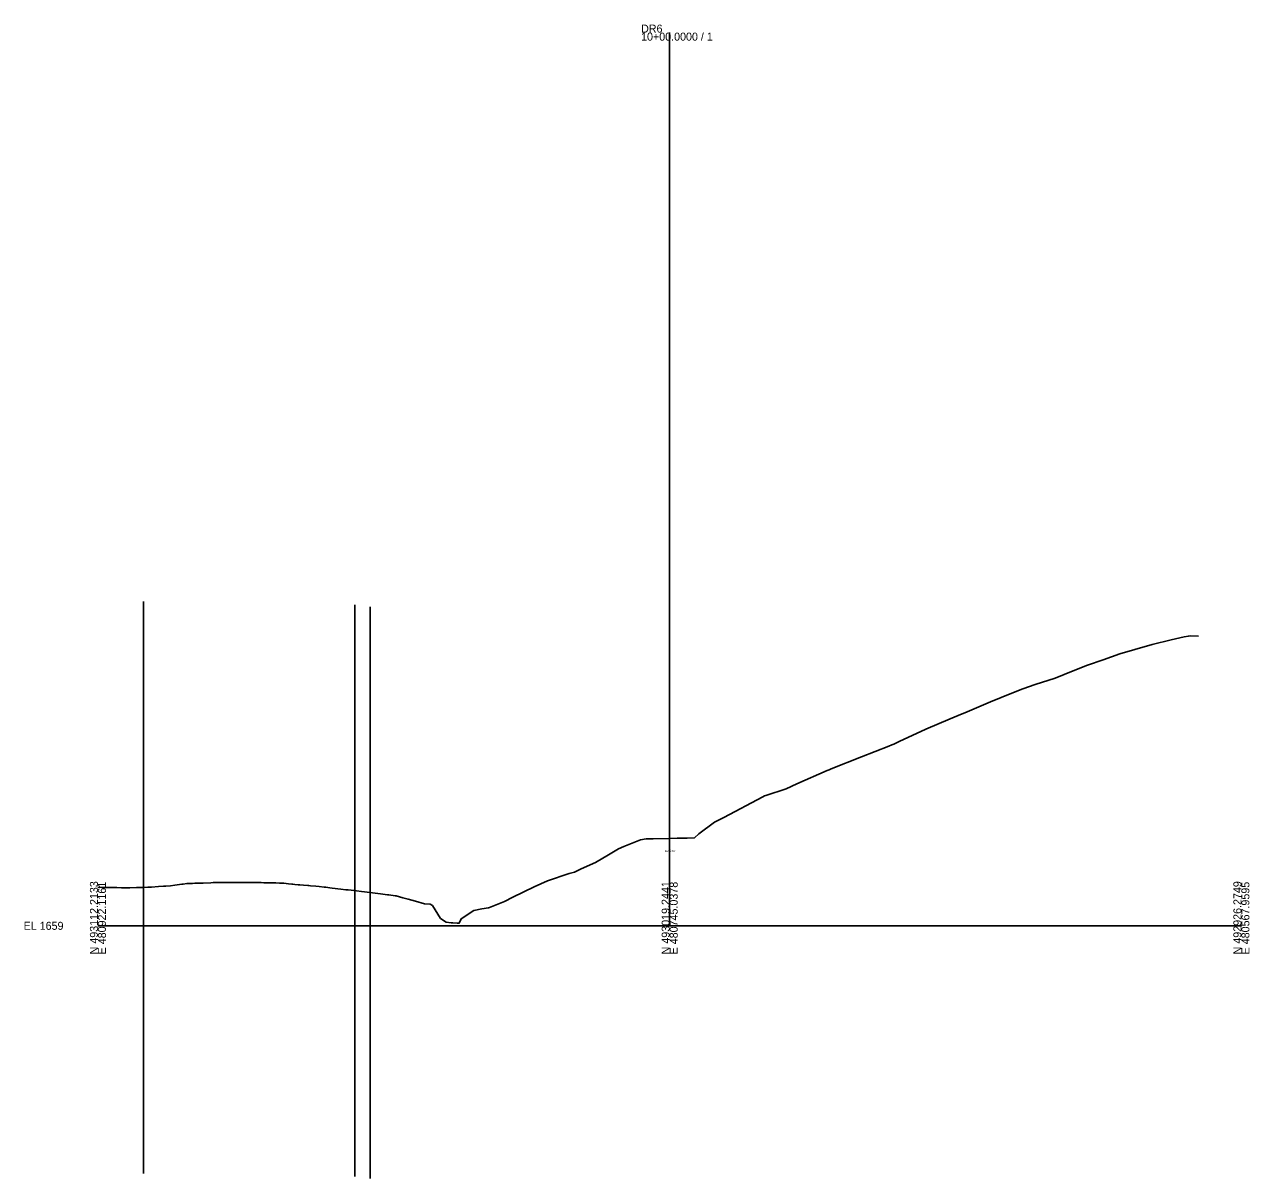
# Model space of a CAD drawing. Extents: x -26 to 403, y -88 to 5647.
# Drawn here: x -25.7 to 402.8, y -88.4 to 315.3 of the extents above; entities that cross this region are included whole.
import ezdxf

# ---------------------------------------------------------------- set-up
doc = ezdxf.new("R2010")
doc.units = 0
for name, color, linetype in [('Exist Cross Section Cell', 7, 'Continuous'), ('Exist XS Center Line Elevation Label', 7, 'Continuous'), ('Exist XS Ground Line', 7, 'Continuous'), ('Scratch_Level_7', 7, 'Continuous')]:
    doc.layers.add(name, color=color, linetype=linetype)

msp = doc.modelspace()

# ---------------------------------------------------------------- linework, layer by layer
at = {"layer": 'Exist Cross Section Cell'}
for p, q in [((200, 0), (200, 312.43)), ((0, 0), (200, 0)), ((200, 0), (400, 0))]:
    msp.add_line(p, q, dxfattribs=at)
at = {"layer": 'Exist XS Ground Line'}
msp.add_lwpolyline([(0, 13.47), (1.57, 13.39), (2.78, 13.37), (6.6, 13.35), (8.19, 13.31), (11.21, 13.33), (13.47, 13.36), (16.05, 13.41), (17.41, 13.47), (17.91, 13.51), (18.69, 13.55), (21.21, 13.7), (22.9, 13.81), (23.32, 13.84), (23.78, 13.88), (25.37, 14.04), (26.9, 14.19), (29.39, 14.51), (29.8, 14.56), (31.11, 14.76), (31.79, 14.8), (33.09, 14.85), (33.9, 14.88), (34.85, 14.91), (36.76, 14.97), (39.53, 15.08), (40.36, 15.1), (42.42, 15.11), (42.96, 15.11), (45.26, 15.12), (45.93, 15.13), (47.31, 15.14), (48.1, 15.14), (48.86, 15.14), (50.81, 15.15), (52.65, 15.13), (53.33, 15.12), (53.71, 15.12), (55.28, 15.1), (56.54, 15.09), (57.13, 15.09), (58.08, 15.08), (59.36, 15.07), (61.7, 15.03), (62.2, 15.02), (63.53, 14.95), (63.89, 14.94), (64.99, 14.86), (66.63, 14.7), (67.81, 14.59), (68.15, 14.56), (68.85, 14.5), (70.07, 14.39), (70.65, 14.34), (71.89, 14.24), (73.44, 14.09), (73.75, 14.07), (74.35, 14.01), (76.22, 13.84), (77.41, 13.72), (79.08, 13.53), (79.72, 13.46), (81.17, 13.29), (81.93, 13.19), (84.93, 12.84), (86.69, 12.64), (87.58, 12.53), (88.6, 12.41), (90.4, 12.2), (92.22, 11.99), (93.2, 11.87), (96.08, 11.5), (97.95, 11.27), (98.8, 11.17), (101.28, 10.88), (101.77, 10.82), (103.94, 10.53), (104.28, 10.48), (106.64, 9.83), (108.57, 9.31), (111.08, 8.58), (114.22, 7.74), (116.18, 7.55), (117.02, 7.15), (119.81, 2.58), (121.86, 1.22), (123.57, 1.02), (124.11, 1.02), (125.67, 0.93), (126.4, 0.95), (127.05, 2.44), (131.49, 5.4), (134.35, 5.91), (136.67, 6.27), (137, 6.37), (142.25, 8.47), (145.08, 10.04), (152.62, 13.59), (157.28, 15.69), (164.85, 18.29), (166.66, 18.81), (169.06, 19.93), (174.07, 22.17), (178.6, 24.83), (182.12, 26.97), (184.02, 27.74), (189.81, 30.06), (191.76, 30.4), (194.28, 30.45), (200, 30.57), (202.61, 30.63), (205, 30.67), (206.18, 30.7), (208.68, 30.83), (210.19, 32.18), (215.72, 36.23), (218.92, 37.85), (232.54, 45.06), (233.18, 45.41), (233.61, 45.57), (240.74, 47.9), (244.48, 49.65), (255.13, 54.34), (255.77, 54.59), (256.48, 54.89), (267.07, 59.11), (276.65, 62.89), (277.77, 63.33), (278.37, 63.59), (280.27, 64.43), (289.66, 68.77), (298.16, 72.38), (300.96, 73.57), (304.05, 74.84), (312.26, 78.29), (319.68, 81.36), (323.55, 82.88), (327.83, 84.38), (334.85, 86.6), (341.2, 89.18), (346.15, 91.21), (351.62, 93.09), (357.44, 95.18), (362.71, 96.61), (368.74, 98.35), (375.4, 99.98), (380.04, 101.12), (381.48, 101.36), (382.18, 101.46), (385.04, 101.34)], dxfattribs=at)
at = {"layer": 'Scratch_Level_7'}
for p, q in [((15.93, 113.41), (15.93, -86.59)), ((89.89, 112.26), (89.89, -87.74)), ((95.25, 111.61), (95.25, -88.39))]:
    msp.add_line(p, q, dxfattribs=at)

# ---------------------------------------------------------------- texts
at = {"layer": 'Exist Cross Section Cell'}
for s, p in [('DR6', (190, 312.43)), ('10+00.0000 / 1', (190, 309.63)), ('EL 1659', (-26, -1.4))]:
    msp.add_text(s, height=2.8, dxfattribs=at).set_placement(p)
for s, p in [('N 493112.2133', (0, -10)), ('E 480922.1161', (2.8, -10)), ('N 493019.2441', (200, -10)), ('E 480745.0378', (202.8, -10)), ('N 492926.2749', (400, -10)), ('E 480567.9595', (402.8, -10))]:
    msp.add_text(s, height=2.8, rotation=90, dxfattribs=at).set_placement(p)
at = {"layer": 'Exist XS Center Line Elevation Label'}
msp.add_text('1689.57', height=0.75, dxfattribs=at).set_placement((198.28, 25.82))

doc.saveas('drawing.dxf')
